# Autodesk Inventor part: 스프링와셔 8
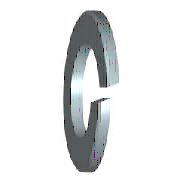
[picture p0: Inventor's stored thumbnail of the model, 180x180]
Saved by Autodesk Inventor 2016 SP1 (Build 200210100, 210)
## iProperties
IsCustomPart: 1
Created: 2012-02
Part Number: 스프링와셔 8
Material: 강철, 연강
Description: 스프링 잠금 와셔
Document SubType Name: Modeling
Standard: KS B 1324
Designer: mduedu
Standards Organization: KS
Language: ko-KR
Size Designation: 번호 3 - 8
Categories: <MemberInstance><Categories><Category DisplayName="조임쇠" InternalName="e4da775c-781d-43d5-af7c-5136215cf5a6" Mnemonic="FSTN"><Category DisplayName="와셔" InternalN
Density: 1 g/cm^3
Appearance: 파란색 - 벽 페인트 - 광택
Author: mduedu
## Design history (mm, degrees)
sketch "스케치1"
  geometry: C1 r 7.4 at (0, 0); C2 r 4.1 at (0, 0); 1 further point
  constraints: 2 centre point, 2 coincident
  dimensions: "d0" = 8.2 diameter of C2 (= SD1); "d1" = 14.8 diameter of C1 (= SD2)
extrude "본체" new body sketch "스케치1" distance "d2" = 2.5 (= SD); taper "d3" = 0 deg
sketch "스케치2"
  geometry: L1 (0, -4.1)-(0, 4.1) reference; L2 (2.5, 7.4)-(2.5, -7.4) reference; L3 (-1.2, 0)-(7.2, 0) reference; L4 (0, -0.5)-(2.5, 0.41); L5 (0, 0.5)-(2.5, 1.41)
  constraints: 4 end point, 4 point on line, 1 parallel
  dimensions: "d4" = 0.5 distance from line of L3 L4.start (= 0.2 x SD); "d5" = 0.5 distance from line of L3 L5.start (= 0.2 x SD); "d6" = 70 deg angle of L2 L4 (= FAWI)
extrude "절단부" cut sketch "스케치2" stored distance "d7" = 2.5 (= SD); taper "d8" = 0 deg
workaxis "Work Axis1"
workplane "Work Plane1"
body "Solid1"
other parameters: "SD1" = 8.2 [user parameter; used in 1 equation term], "SD2" = 14.8 [user parameter; used in 1 equation term], "SD" = 2.5 [user parameter; used in 4 equation terms], "FAWI" = 70 deg [user parameter; used in 1 equation term], "d9" = 0, "d10" = 0, "d11" = 0, "d12" = 0, "SDI" = 3.3 [user parameter], "NND" = 8 [user parameter]
